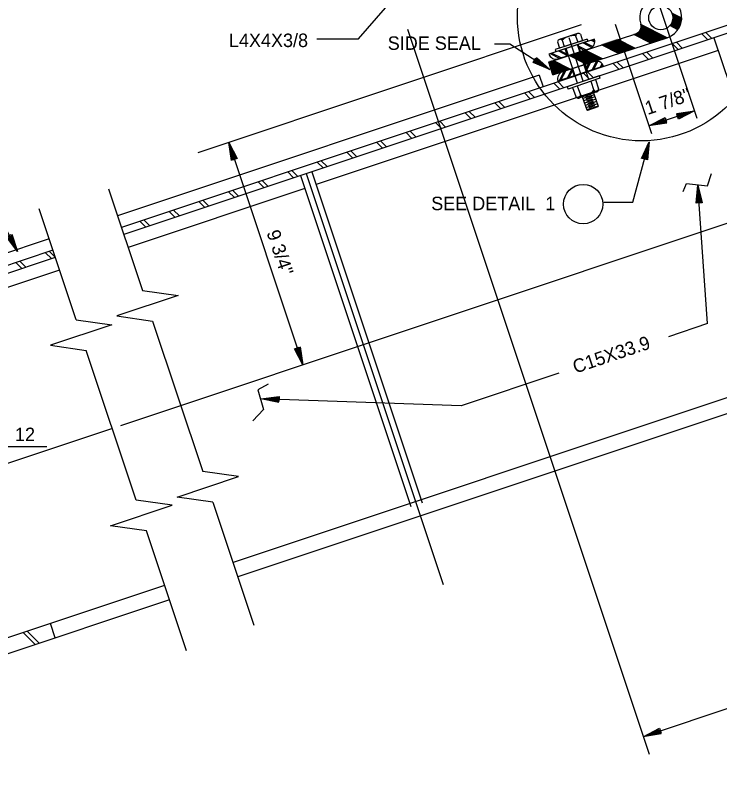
# Model space of a CAD drawing. Extents: x 0.1 to 13.5, y 0.1 to 9.5.
# Drawn here: x 4.972 to 7.414, y 5.175 to 7.802 of the extents above; entities that cross this region are included whole.
import ezdxf

# ---------------------------------------------------------------- set-up
doc = ezdxf.new("R2010")
doc.units = 0
for name, color, linetype in [('Level 1', 7, 'Continuous'), ('Level 10', 7, 'Continuous'), ('Level 13', 7, 'Continuous'), ('Level 2', 7, 'Continuous'), ('Level 25', 7, 'Continuous'), ('Level 3', 7, 'Continuous'), ('Level 44', 7, 'Continuous'), ('Level 50', 7, 'Continuous')]:
    doc.layers.add(name, color=color, linetype=linetype)

msp = doc.modelspace()

# ---------------------------------------------------------------- linework, layer by layer
at = {"layer": 'Level 1'}
for p, q in [((6.3319, 7.7536), (7.169, 5.2424)), ((7.0508, 7.7711), (7.1771, 7.392)), ((6.9655, 7.6872), (6.851, 7.65)), ((6.9808, 7.6427), (6.8663, 7.6055)), ((5.7121, 7.3615), (5.9691, 6.5907))]:
    msp.add_line(p, q, dxfattribs=at)
for centre, start, end in [((6.9551, 7.7112), 288, 18), ((6.8461, 7.6758), 198, 288), ((6.9865, 7.6172), 18, 108), ((6.8775, 7.5818), 108, 198)]:
    msp.add_arc(centre, 0.026, start, end, dxfattribs=at)
at = {"layer": 'Level 10'}
for p, q in [((6.9399, 7.7063), (6.9709, 7.6905)), ((6.9456, 7.7081), (6.9742, 7.6935)), ((6.968, 7.7154), (6.981, 7.7088)), ((6.9736, 7.7172), (6.981, 7.7134)), ((6.8544, 7.6785), (6.885, 7.6629)), ((6.86, 7.6803), (6.8832, 7.6685)), ((6.9256, 7.6949), (6.9503, 7.6823)), ((6.9275, 7.6893), (6.9447, 7.6805)), ((6.8264, 7.6694), (6.8592, 7.6527)), ((6.832, 7.6712), (6.8648, 7.6545)), ((6.9512, 7.6187), (6.96, 7.636)), ((6.953, 7.6131), (6.9656, 7.6378)), ((6.9713, 7.6123), (6.9871, 7.6432)), ((6.9769, 7.6141), (6.9915, 7.6428)), ((6.9993, 7.6214), (7.006, 7.6344)), ((7.0049, 7.6232), (7.0087, 7.6307)), ((6.8578, 7.5754), (6.8745, 7.6082)), ((6.8634, 7.5772), (6.8801, 7.61)), ((6.8858, 7.5845), (6.9014, 7.6151)), ((6.8914, 7.5863), (6.9032, 7.6095))]:
    msp.add_line(p, q, dxfattribs=at)
at = {"layer": 'Level 13'}
for p, q in [((7.2822, 7.7915), (7.248, 7.8089)), ((7.282, 7.7887), (7.2493, 7.8054)), ((7.2764, 7.7652), (7.2485, 7.7795)), ((7.2774, 7.7676), (7.2497, 7.7818)), ((7.2783, 7.7701), (7.25, 7.7846)), ((7.2818, 7.7859), (7.2501, 7.802)), ((7.2791, 7.7726), (7.2505, 7.7873)), ((7.2815, 7.7831), (7.2506, 7.7988)), ((7.2799, 7.7752), (7.2508, 7.79)), ((7.281, 7.7804), (7.2509, 7.7958)), ((7.2805, 7.7778), (7.2509, 7.7928)), ((7.2101, 7.7172), (7.1393, 7.7533)), ((7.2311, 7.724), (7.1402, 7.7704)), ((7.2137, 7.7183), (7.1405, 7.7556)), ((7.2171, 7.7195), (7.1408, 7.7584)), ((7.2277, 7.7229), (7.1409, 7.7671)), ((7.2207, 7.7206), (7.1411, 7.7611)), ((7.2241, 7.7217), (7.1412, 7.764)), ((7.2689, 7.7516), (7.2405, 7.766)), ((7.2703, 7.7537), (7.2422, 7.7681)), ((7.2717, 7.7559), (7.2438, 7.7702)), ((7.2729, 7.7583), (7.2452, 7.7724)), ((7.2743, 7.7605), (7.2464, 7.7747)), ((7.2754, 7.7628), (7.2476, 7.777)), ((6.821, 7.6401), (7.1232, 7.7382)), ((6.921, 7.7389), (6.8578, 7.7184)), ((6.9144, 7.7311), (6.9218, 7.7085)), ((6.9309, 7.7362), (6.9381, 7.7138)), ((7.1751, 7.7058), (7.1161, 7.7359)), ((7.1786, 7.7069), (7.1196, 7.737)), ((7.1821, 7.7081), (7.123, 7.7382)), ((7.1856, 7.7092), (7.1263, 7.7395)), ((7.1891, 7.7104), (7.1291, 7.741)), ((7.1926, 7.7115), (7.1314, 7.7427)), ((7.1961, 7.7126), (7.1335, 7.7445)), ((7.1996, 7.7138), (7.1353, 7.7465)), ((7.2031, 7.7149), (7.1369, 7.7487)), ((7.2066, 7.716), (7.1381, 7.751)), ((6.8355, 7.5955), (7.2318, 7.7242)), ((6.9546, 7.7192), (6.8436, 7.6831)), ((6.957, 7.7118), (6.846, 7.6758)), ((6.8516, 7.7105), (6.8589, 7.6881)), ((6.9381, 7.7138), (6.8589, 7.6881)), ((6.8676, 7.7158), (6.8749, 7.6933)), ((6.9604, 7.58), (6.9213, 7.7002)), ((6.9546, 7.7192), (6.957, 7.7118)), ((7.063, 7.6694), (7.004, 7.6995)), ((7.0665, 7.6705), (7.0075, 7.7006)), ((7.07, 7.6717), (7.011, 7.7018)), ((7.0735, 7.6728), (7.0145, 7.7029)), ((7.0771, 7.6739), (7.018, 7.704)), ((7.0805, 7.6751), (7.0215, 7.7052)), ((7.084, 7.6762), (7.025, 7.7063)), ((7.0876, 7.6774), (7.0285, 7.7074)), ((7.0911, 7.6785), (7.032, 7.7086)), ((7.0945, 7.6796), (7.0355, 7.7097)), ((7.0981, 7.6808), (7.039, 7.7109)), ((7.1016, 7.6819), (7.0425, 7.712)), ((7.1051, 7.683), (7.046, 7.7131)), ((7.1085, 7.6842), (7.0495, 7.7143)), ((7.1051, 7.683), (7.0506, 7.7108)), ((7.1121, 7.6853), (7.053, 7.7154)), ((7.1156, 7.6865), (7.0565, 7.7166)), ((7.1191, 7.6876), (7.06, 7.7177)), ((6.8436, 7.6831), (6.846, 7.6758)), ((6.9208, 7.5668), (6.8817, 7.6873)), ((6.9825, 7.6432), (6.9234, 7.6733)), ((6.986, 7.6443), (6.9269, 7.6744)), ((6.9895, 7.6455), (6.9304, 7.6756)), ((6.993, 7.6466), (6.9339, 7.6767)), ((6.9965, 7.6478), (6.9374, 7.6779)), ((7, 7.6489), (6.9409, 7.679)), ((7.0035, 7.65), (6.9444, 7.6801)), ((7.007, 7.6512), (6.9479, 7.6813)), ((6.951, 7.633), (6.8919, 7.6631)), ((6.9544, 7.6341), (6.8954, 7.6642)), ((6.9579, 7.6352), (6.8989, 7.6653)), ((6.9615, 7.6364), (6.9024, 7.6665)), ((6.965, 7.6375), (6.9059, 7.6676)), ((6.9685, 7.6386), (6.9094, 7.6688)), ((6.972, 7.6398), (6.9129, 7.6699)), ((6.9755, 7.6409), (6.9164, 7.671)), ((6.979, 7.6421), (6.9199, 7.6722)), ((6.8355, 7.5955), (6.821, 7.6401)), ((6.8809, 7.6102), (6.8218, 7.6403)), ((6.8774, 7.6091), (6.8219, 7.6373)), ((6.8739, 7.6079), (6.8231, 7.6338)), ((6.8704, 7.6068), (6.8242, 7.6303)), ((6.8669, 7.6057), (6.8253, 7.6268)), ((6.8844, 7.6113), (6.8254, 7.6414)), ((6.8634, 7.6045), (6.8265, 7.6233)), ((6.8879, 7.6125), (6.8288, 7.6426)), ((6.8914, 7.6136), (6.8323, 7.6437)), ((6.8949, 7.6148), (6.8359, 7.6449)), ((6.8599, 7.6034), (6.8276, 7.6198)), ((6.8564, 7.6022), (6.8288, 7.6163)), ((6.8529, 7.6011), (6.8299, 7.6128)), ((6.8494, 7.6), (6.831, 7.6093)), ((6.8459, 7.5988), (6.8322, 7.6058)), ((6.8424, 7.5977), (6.8333, 7.6023)), ((6.8389, 7.5966), (6.8344, 7.5988)), ((6.9958, 7.5924), (6.8854, 7.5544)), ((6.9985, 7.5844), (6.8882, 7.5465)), ((6.9664, 7.5734), (6.9773, 7.542)), ((6.9827, 7.579), (6.9936, 7.5476)), ((6.9958, 7.5924), (6.9985, 7.5844)), ((6.8854, 7.5544), (6.8882, 7.5465)), ((6.9039, 7.5519), (6.9148, 7.5204)), ((6.9198, 7.5574), (6.9307, 7.5259)), ((6.9882, 7.5369), (6.9254, 7.5153)), ((6.9372, 7.5193), (6.9527, 7.4742)), ((6.9786, 7.5269), (6.9392, 7.5133)), ((6.9813, 7.5191), (6.9419, 7.5055)), ((6.9674, 7.5275), (6.9468, 7.5204)), ((6.9701, 7.5196), (6.9495, 7.5124)), ((6.9766, 7.5329), (6.9922, 7.4876)), ((6.9841, 7.5111), (6.9447, 7.4976)), ((6.9868, 7.5033), (6.9474, 7.4897)), ((6.9895, 7.4954), (6.9501, 7.4819)), ((6.9728, 7.5117), (6.9522, 7.5046)), ((6.9755, 7.5038), (6.9549, 7.4967)), ((6.9782, 7.4959), (6.9576, 7.4888)), ((6.9527, 7.4742), (6.9554, 7.4727)), ((6.9922, 7.4875), (6.9528, 7.4739)), ((6.9908, 7.4849), (6.9554, 7.4727)), ((6.981, 7.488), (6.9603, 7.4809)), ((6.9922, 7.4876), (6.9908, 7.4849))]:
    msp.add_line(p, q, dxfattribs=at)
for points in [[(5.4127, 6.8489), (5.5371, 6.8315), (5.3239, 6.7604), (5.4482, 6.7426)], [(5.1829, 6.7476), (5.3073, 6.7302), (5.0941, 6.6591), (5.2184, 6.6413)], [(5.6572, 6.1154), (5.5328, 6.1329), (5.746, 6.2039), (5.6218, 6.2218)], [(5.4266, 6.0166), (5.3023, 6.034), (5.5155, 6.1051), (5.3912, 6.1229)]]:
    msp.add_lwpolyline(points, dxfattribs=at)
msp.add_circle((7.2093, 7.7936), 0.0417, dxfattribs=at)
for centre, radius, start, end in [((7.2093, 7.7936), 0.0729, 288, 198), ((7.1152, 7.763), 0.026, 288, 18), ((6.9071, 7.6746), 0.0569, 82.5519, 133.884), ((6.9238, 7.73), 0.00938, 41.1675, 173.9991), ((6.8607, 7.7097), 0.00912, 40.375, 175.1995), ((6.9435, 7.5644), 0.0406, 251.4343, 326.5657), ((6.9855, 7.5449), 0.00844, 199.5659, 18.4341), ((6.9227, 7.5233), 0.00843, 199.4975, 18.5025)]:
    msp.add_arc(centre, radius, start, end, dxfattribs=at)
at = {"layer": 'Level 2'}
for p, q in [((6.9798, 7.7193), (6.8213, 7.6678)), ((6.9317, 7.6763), (6.9236, 7.701)), ((6.8856, 7.6612), (6.8775, 7.686)), ((7.0112, 7.6253), (6.8527, 7.5738)), ((6.947, 7.6318), (6.955, 7.607)), ((6.9009, 7.6168), (6.9089, 7.592))]:
    msp.add_line(p, q, dxfattribs=at)
at = {"layer": 'Level 25'}
for p, q in [((7.3353, 7.4447), (7.0635, 8.2601)), ((7.4448, 7.7689), (5.3399, 7.0673)), ((6.9339, 7.7688), (5.6051, 7.3258)), ((7.4728, 7.7508), (5.3482, 7.0426)), ((6.9406, 7.5734), (6.8916, 7.7243)), ((7.3938, 7.7244), (7.7891, 6.5386)), ((7.4086, 7.6799), (6.0152, 7.2155)), ((6.7884, 7.594), (5.3268, 7.1068)), ((6.7884, 7.594), (6.8016, 7.5545)), ((7.3264, 7.4714), (7.1682, 7.4187)), ((8.532, 7.445), (5.337, 6.38)), ((5.9806, 7.2534), (6.455, 5.8304)), ((6.0004, 7.26), (6.3825, 6.1136)), ((7.3715, 7.2112), (7.3856, 7.2536)), ((5.9609, 7.2468), (6.343, 6.1005)), ((5.2952, 7.2014), (5.4127, 6.8489)), ((5.9757, 7.2023), (5.363, 6.9981)), ((7.2868, 7.1914), (7.2981, 7.2197)), ((7.2981, 7.2197), (7.3715, 7.2112)), ((7.3714, 6.7339), (7.3376, 7.214)), ((5.1829, 6.7476), (5.0552, 7.131)), ((5.0896, 7.0277), (4.7402, 6.9113)), ((5.1028, 6.9882), (3.6347, 6.4989)), ((5.111, 6.9635), (3.6139, 6.4644)), ((5.1258, 6.919), (3.6972, 6.4428)), ((5.4482, 6.7426), (5.6218, 6.2218)), ((7.3714, 6.7339), (7.2358, 6.6887)), ((5.3912, 6.1229), (5.2184, 6.6413)), ((7.7726, 6.588), (5.727, 5.9061)), ((7.8681, 6.5649), (5.7435, 5.8567)), ((6.8562, 6.5621), (6.5172, 6.4491)), ((5.8491, 6.5244), (5.8124, 6.5046)), ((5.8124, 6.5046), (5.8321, 6.4367)), ((6.5172, 6.4491), (5.8237, 6.4735)), ((5.8321, 6.4367), (5.7954, 6.3972)), ((5.3086, 6.3706), (3.6139, 5.8056)), ((4.9312, 6.3083), (5.0816, 6.3083)), ((5.6572, 6.1154), (5.7992, 5.6896)), ((5.5655, 5.6001), (5.4266, 6.0166)), ((9.0362, 5.9324), (7.1487, 5.3032)), ((5.4898, 5.827), (3.6972, 5.2295)), ((5.5063, 5.7776), (3.6972, 5.1746)), ((5.111, 5.6459), (5.0945, 5.6953))]:
    msp.add_line(p, q, dxfattribs=at)
for centre, radius in [((7.1424, 7.7968), 0.4297), ((6.9404, 7.1481), 0.0682)]:
    msp.add_circle(centre, radius, dxfattribs=at)
at = {"layer": 'Level 3'}
for p, q in [((6.8107, 7.6234), (6.8107, 7.6234)), ((6.8253, 7.6141), (6.8253, 7.6141)), ((7.1691, 7.3638), (7.1691, 7.3638)), ((7.1645, 7.347), (7.1645, 7.347)), ((4.972, 6.9989), (4.972, 6.9989)), ((4.9799, 6.9835), (4.9799, 6.9835))]:
    msp.add_line(p, q, dxfattribs=at)
for points in [[(6.0169, 7.72), (6.1613, 7.72), (6.3177, 7.9005)], [(6.6329, 7.7032), (6.6858, 7.7032), (6.8253, 7.6141)], [(6.7784, 7.6563), (6.8253, 7.6141), (6.7672, 7.6389), (6.7767, 7.6538), (6.8107, 7.6234), (6.7713, 7.6403), (6.7774, 7.6499), (6.7967, 7.6324), (6.7753, 7.6417), (6.7778, 7.6456), (6.7821, 7.6417)], [(7.0123, 7.1546), (7.1124, 7.1546), (7.1691, 7.3638)], [(7.1428, 7.3063), (7.1691, 7.3638), (7.1628, 7.3009), (7.1457, 7.3055), (7.1645, 7.347), (7.1602, 7.3043), (7.1493, 7.3073), (7.1602, 7.3309), (7.1577, 7.3078), (7.1532, 7.309), (7.1556, 7.3142)], [(4.7248, 7.3542), (4.7898, 7.3542), (4.9799, 6.9835)], [(4.9606, 7.0437), (4.9799, 6.9835), (4.9422, 7.0343), (4.958, 7.0423), (4.972, 6.9989), (4.9464, 7.0334), (4.9565, 7.0386), (4.9644, 7.0138), (4.9506, 7.0326), (4.9548, 7.0347), (4.9564, 7.0292)]]:
    msp.add_lwpolyline(points, dxfattribs=at)
at = {"layer": 'Level 44'}
for p, q in [((7.3723, 7.7173), (7.3517, 7.7378)), ((7.3864, 7.722), (7.3658, 7.7426)), ((7.2697, 7.6831), (7.2492, 7.7037)), ((7.2839, 7.6878), (7.2633, 7.7084)), ((7.1814, 7.6536), (7.1608, 7.6742)), ((7.1672, 7.6489), (7.1466, 7.6695)), ((7.0647, 7.6147), (7.0441, 7.6353)), ((7.0788, 7.6194), (7.0582, 7.64)), ((6.9621, 7.5806), (6.9416, 7.6011)), ((6.9763, 7.5853), (6.9557, 7.6058)), ((6.8738, 7.5511), (6.8532, 7.5717)), ((6.8596, 7.5464), (6.839, 7.567)), ((6.7571, 7.5122), (6.7365, 7.5328)), ((6.7712, 7.5169), (6.7506, 7.5375)), ((6.6546, 7.478), (6.634, 7.4986)), ((6.6687, 7.4827), (6.6481, 7.5033)), ((6.552, 7.4438), (6.5314, 7.4644)), ((6.5662, 7.4486), (6.5456, 7.4691)), ((6.4495, 7.4097), (6.4289, 7.4303)), ((6.4636, 7.4144), (6.4431, 7.435)), ((6.347, 7.3755), (6.3264, 7.3961)), ((6.3611, 7.3802), (6.3405, 7.4008)), ((6.2444, 7.3413), (6.2239, 7.3619)), ((6.2586, 7.346), (6.238, 7.3666)), ((6.156, 7.3119), (6.1355, 7.3324)), ((6.1419, 7.3071), (6.1213, 7.3277)), ((6.0394, 7.273), (6.0188, 7.2935)), ((6.0535, 7.2777), (6.0329, 7.2983)), ((5.9368, 7.2388), (5.9163, 7.2594)), ((5.951, 7.2435), (5.9304, 7.2641)), ((5.8485, 7.2093), (5.8279, 7.2299)), ((5.8343, 7.2046), (5.8137, 7.2252)), ((5.7318, 7.1704), (5.7112, 7.191)), ((5.7459, 7.1751), (5.7253, 7.1957)), ((5.6293, 7.1363), (5.6087, 7.1568)), ((5.6434, 7.141), (5.6228, 7.1616)), ((5.5267, 7.1021), (5.5061, 7.1227)), ((5.5409, 7.1068), (5.5203, 7.1274)), ((5.4242, 7.0679), (5.4036, 7.0885)), ((5.4383, 7.0726), (5.4178, 7.0932)), ((5.0975, 6.959), (5.0769, 6.9796)), ((5.1106, 6.9647), (5.091, 6.9843)), ((4.995, 6.9248), (4.9744, 6.9454)), ((5.0091, 6.9295), (4.9885, 6.9501)), ((5.0408, 5.6225), (4.9996, 5.6636)), ((5.0549, 5.6272), (5.0138, 5.6683))]:
    msp.add_line(p, q, dxfattribs=at)
at = {"layer": 'Level 50'}
for p, q in [((7.3099, 7.466), (7.3099, 7.466)), ((7.3264, 7.4714), (7.3264, 7.4714)), ((7.1682, 7.4187), (7.1682, 7.4187)), ((7.1847, 7.4242), (7.1847, 7.4242)), ((5.7121, 7.3615), (5.7121, 7.3615)), ((5.7176, 7.3451), (5.7176, 7.3451)), ((7.3376, 7.214), (7.3376, 7.214)), ((7.3388, 7.1967), (7.3388, 7.1967)), ((5.9636, 6.6071), (5.9636, 6.6071)), ((5.9691, 6.5907), (5.9691, 6.5907)), ((5.8237, 6.4735), (5.8237, 6.4735)), ((5.841, 6.4729), (5.841, 6.4729)), ((7.1652, 5.3087), (7.1652, 5.3087)), ((7.1487, 5.3032), (7.1487, 5.3032))]:
    msp.add_line(p, q, dxfattribs=at)
for points in [[(7.264, 7.4615), (7.3264, 7.4714), (7.2705, 7.4419), (7.2649, 7.4587), (7.3099, 7.466), (7.272, 7.4459), (7.2684, 7.4567), (7.2941, 7.4607), (7.2735, 7.4499), (7.272, 7.4544), (7.2777, 7.4552)], [(7.2306, 7.4286), (7.1682, 7.4187), (7.2241, 7.4482), (7.2297, 7.4315), (7.1847, 7.4242), (7.2226, 7.4442), (7.2262, 7.4335), (7.2005, 7.4295), (7.2212, 7.4402), (7.2226, 7.4358), (7.2169, 7.435)], [(5.722, 7.2991), (5.7121, 7.3615), (5.7416, 7.3057), (5.7249, 7.3001), (5.7176, 7.3451), (5.7376, 7.3071), (5.7269, 7.3035), (5.7229, 7.3293), (5.7336, 7.3086), (5.7292, 7.3071), (5.7283, 7.3128)], [(7.3317, 7.1511), (7.3376, 7.214), (7.3523, 7.1526), (7.3347, 7.1513), (7.3388, 7.1967), (7.3488, 7.155), (7.3375, 7.1542), (7.34, 7.1801), (7.3453, 7.1574), (7.3406, 7.1571), (7.3412, 7.1628)], [(5.9591, 6.6531), (5.9691, 6.5907), (5.9395, 6.6466), (5.9563, 6.6521), (5.9636, 6.6071), (5.9435, 6.6451), (5.9543, 6.6487), (5.9583, 6.6229), (5.9476, 6.6436), (5.952, 6.6451), (5.9528, 6.6394)], [(5.8856, 6.461), (5.8237, 6.4735), (5.8863, 6.4816), (5.8857, 6.464), (5.841, 6.4729), (5.8835, 6.4784), (5.8831, 6.4671), (5.8576, 6.4723), (5.8808, 6.4751), (5.8806, 6.4705), (5.875, 6.4717)], [(7.2111, 5.3131), (7.1487, 5.3032), (7.2046, 5.3327), (7.2102, 5.316), (7.1652, 5.3087), (7.2031, 5.3287), (7.2067, 5.318), (7.181, 5.314), (7.2016, 5.3247), (7.2031, 5.3203), (7.1974, 5.3195)]]:
    msp.add_lwpolyline(points, dxfattribs=at)

# ---------------------------------------------------------------- texts
at = {"layer": 'Level 1'}
for s, p in [('L4X4X3/8', (5.7126, 7.6919)), ('SIDE SEAL', (6.263, 7.6822))]:
    msp.add_text(s, height=0.0467, dxfattribs=at).set_placement(p)
for s, rotation, p in [("1 7/8''", 18.4338, (7.1639, 7.4563)), ('C15X33.9', 18.435, (6.9135, 6.5607))]:
    msp.add_text(s, height=0.0467, rotation=rotation, dxfattribs=at).set_placement(p)
at = {"layer": 'Level 25'}
for s, height, p in [('SEE DETAIL  1', 0.046698, (6.4137, 7.1269)), ('12', 0.0467, (4.9711, 6.3269))]:
    msp.add_text(s, height=height, dxfattribs=at).set_placement(p)
msp.add_text('9 3/4"', height=0.0467, rotation=288.4352, dxfattribs=at).set_placement((5.8424, 7.0494))

doc.saveas('drawing.dxf')
